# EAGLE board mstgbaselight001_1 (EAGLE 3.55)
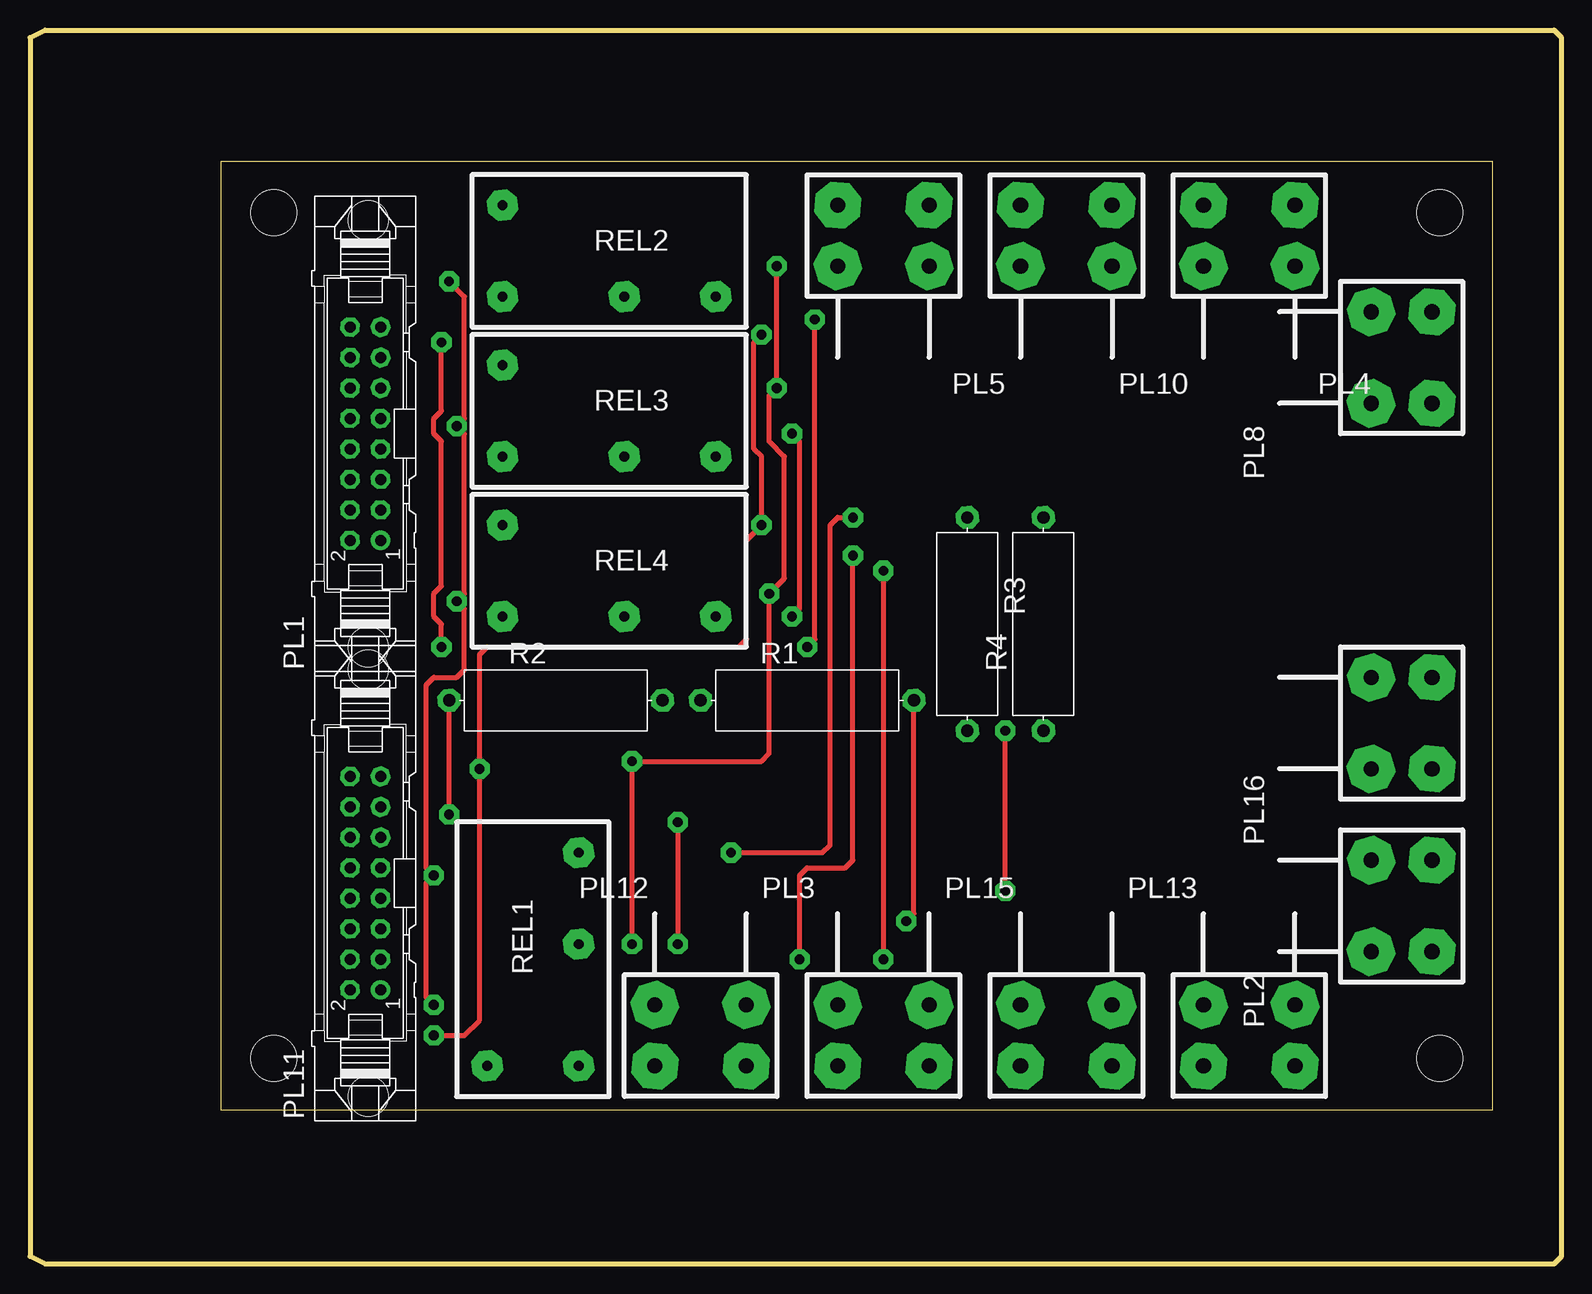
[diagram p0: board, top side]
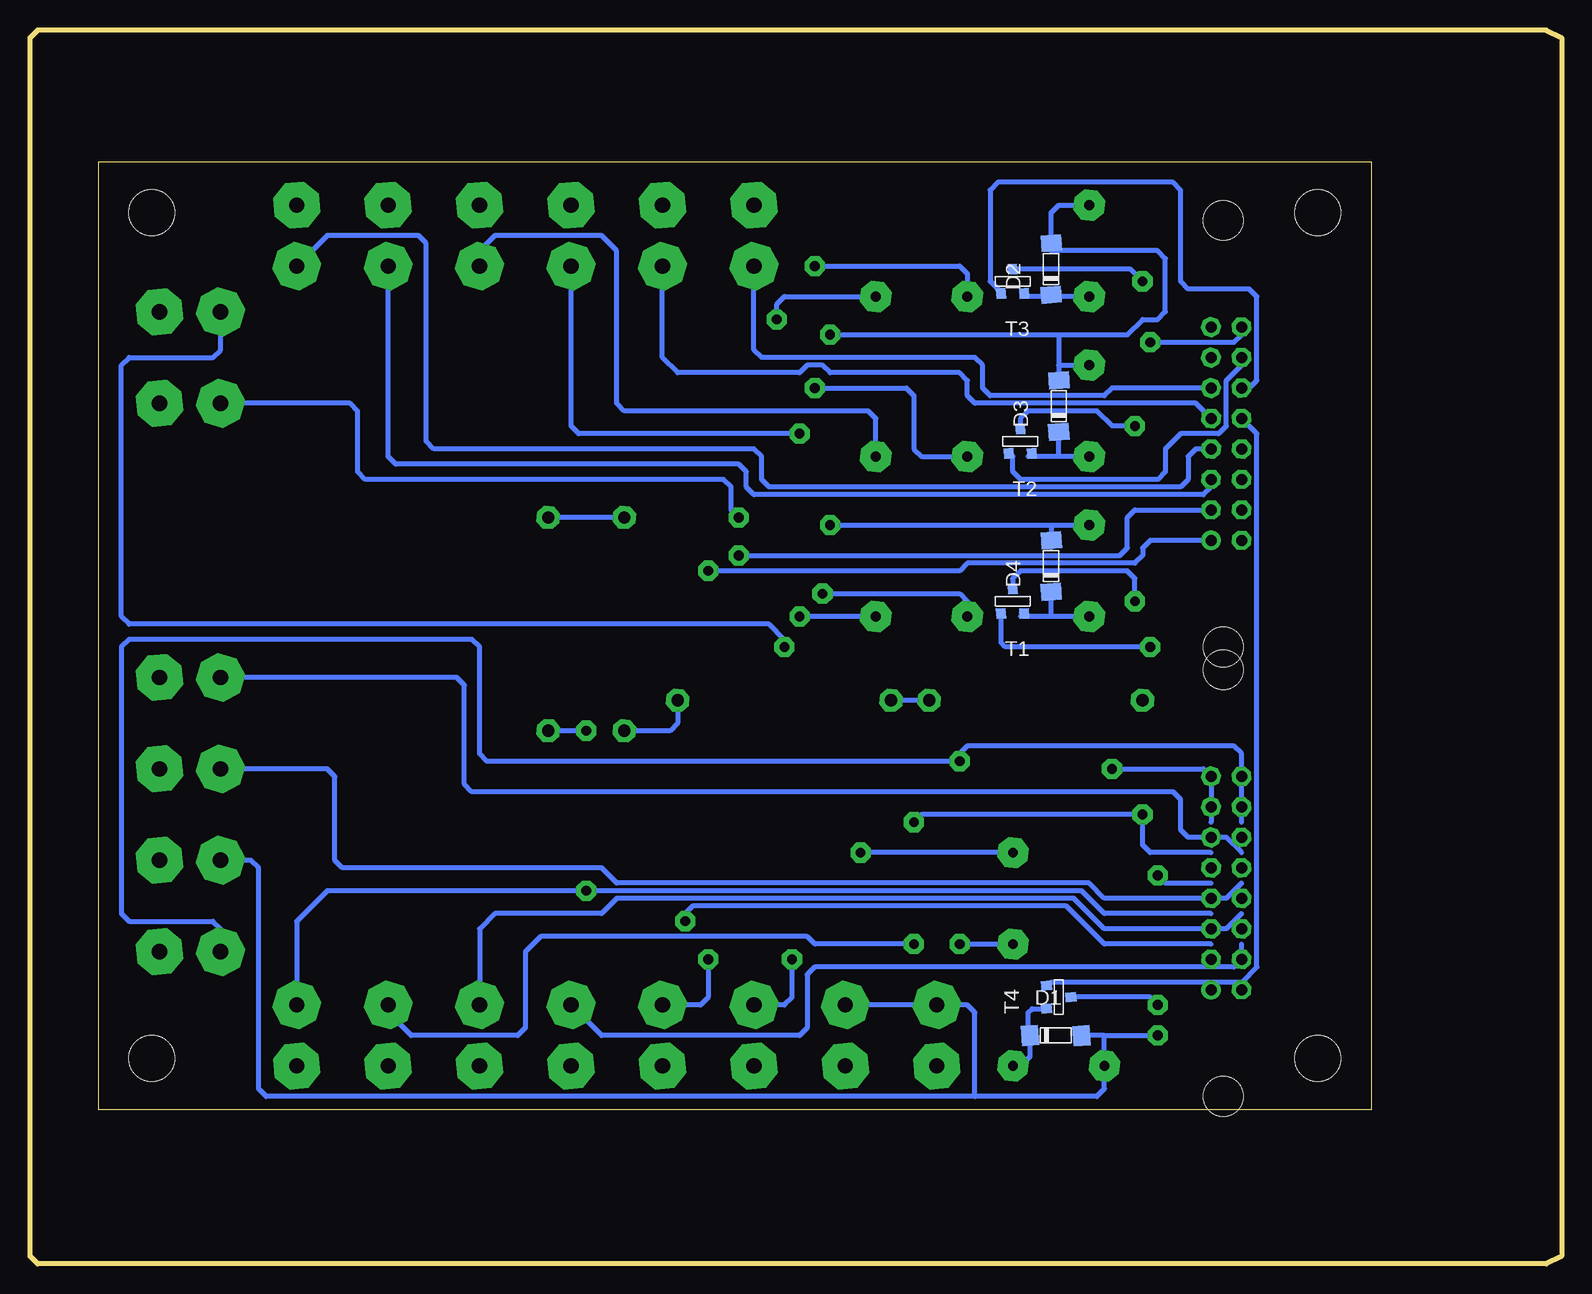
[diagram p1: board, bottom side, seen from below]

Size 127.64 x 102.87 mm. Coordinates in mm from the lower left corner, seen from the top.
Outline: 121.92,12.86 121.92,91.91 15.88,91.91 15.88,12.86 121.92,12.86
Outline: 0,0.63 1.27,0 127,0 127.64,0.63 127.64,102.23 127,102.87 1.27,102.87 0,102.23 0,0.63
Copper layers used: Top, Bottom
Holes 3.81 mm at 20.32,87.63 117.47,87.63 117.47,17.14 20.32,17.14
vRestrict: area 69.9,50.8 to 94,74.9

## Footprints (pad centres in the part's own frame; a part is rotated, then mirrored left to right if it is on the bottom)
D-80 = smd 1.397 x 1.702 rotated 4.4:  -2.388,0 | smd 1.397 x 1.702 rotated 4.3:  1.905,-0.025
V = drill 0.914 pad 1.6 round:  -8.89,-1.27 | drill 0.914 pad 1.6 octagon:  -8.89,1.27;  -6.35,-1.27;  -6.35,1.27;  -3.81,-1.27;  -3.81,1.27;  -1.27,-1.27;  -1.27,1.27;  1.27,-1.27;  1.27,1.27;  3.81,-1.27;  3.81,1.27;  6.35,-1.27;  6.35,1.27;  8.89,-1.27;  8.89,1.27 | hole 3.302: 17.78,-0.254; -17.78,-0.254
3MM = drill 1.27 pad 3.81 octagon:  0,0;  7.62,0;  0,-5.08;  7.62,-5.08
18 = drill 1.016 pad 1.905 octagon:  -8.89,0;  8.89,0
LAIS_R = drill 0.813 pad 2.54 octagon:  -12.7,5.08;  -12.7,-2.54;  -2.54,-2.54;  5.08,-2.54
T-23 = smd 0.787 x 0.889 rotated 4.4:  0.991,1.016 | smd 0.787 x 0.889 rotated 4.3:  -0.94,1.016 | smd 0.787 x 0.889 rotated 4.5:  0.025,-1.016

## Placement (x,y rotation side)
D1  SMD4148  [D-80]  41.91,19.05 0 bottom
D2  SMD4148  [D-80]  42.55,83.19 90 bottom
D3  SMD4148  [D-80]  41.91,71.75 90 bottom
D4  SMD4148  [D-80]  42.55,58.42 90 bottom
PL1  16V  [V]  27.94,69.22 90 top
PL2  6_3MM  [3MM]  111.76,26.04 90 top
PL3  6_3MM  [3MM]  67.31,21.59 0 top
PL4  6_3MM  [3MM]  105.41,83.19 180 top
PL5  6_3MM  [3MM]  74.93,83.19 180 top
PL8  6_3MM  [3MM]  111.76,71.75 90 top
PL10  6_3MM  [3MM]  90.17,83.19 180 top
PL11  10V  [V]  27.94,31.75 90 top
PL12  6_3MM  [3MM]  52.07,21.59 0 top
PL13  6_3MM  [3MM]  97.79,21.59 0 top
PL15  6_3MM  [3MM]  82.55,21.59 0 top
PL16  6_3MM  [3MM]  111.76,41.27 90 top
R1  56R 0,5W  [18]  64.77,46.99 0 top
R2  47R 0,5W  [18]  43.81,46.99 0 top
R3  82R 0,5W  [18]  78.1,53.34 270 top
R4  68R 0,5W  [18]  84.45,53.34 90 top
REL1  REL_RE  [LAIS_R]  43.18,29.21 90 top
REL2  REL_RE  [LAIS_R]  52.07,83.19 0 top
REL3  REL_RE  [LAIS_R]  52.07,69.85 0 top
REL4  REL_RE  [LAIS_R]  52.07,56.52 0 top
T1  FDV301N  [T-23]  45.72,55.25 180 bottom
T2  FDV301N  [T-23]  45.09,68.58 180 bottom
T3  FDV301N  [T-23]  45.72,81.92 180 bottom
T4  FDV301N  [T-23]  41.91,22.23 90 bottom

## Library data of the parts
D1-D4 T1-T4 = smd
PL1 PL11 = pinh-v
PL2-PL5 PL8 PL10 PL12 PL13 PL15 PL16 REL1-REL4 = andit4at
R1-R4 = discrete

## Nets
N$1: PL2. PL11. REL1. REL2. REL3. REL4.
N$2: D1. D2. D3. D4. PL2. PL11. PL12. REL1. REL2. REL3. REL4.
N$3: PL1. T3.
N$4: PL1. T2.
N$5: PL1. T4.
N$6: PL1. T1.
N$7: R3. R4.
N$9: D2. REL2. T3.
N$10: D3. REL3. T2.
N$11: PL10. REL4.
N$12: PL10. REL3.
N$13: PL8. REL2.
N$15: PL8. REL1.
N$16: D1. REL1. T4.
N$17: D4. REL4. T1.
N$18: R1. R2.
N$19: PL11. T1. T2. T3. T4.
N$20: PL11. R1. R3.
N$24: PL1. PL5.
N$25: PL1. PL5.
N$26: PL1. PL4.
N$27: PL1. PL4.
N$28: PL1. PL3.
N$29: PL1. PL3.
N$31: PL11. PL13. R2.
N$33: PL11. PL13. R4.
N$37: PL11. PL16.
N$38: PL11. PL16.
N$39: PL11. PL15.
N$40: PL11. PL15.

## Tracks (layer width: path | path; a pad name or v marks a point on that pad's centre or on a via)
N$1  (via drill 0.81 pad 1.68)
  Top 0.406: v62.23,83.19 v62.23,73.03 61.59,72.39 61.59,68.58 62.87,67.31 62.87,57.15 v61.59,55.88 61.59,42.55 60.96,41.91 v50.16,41.91 v50.16,26.67
  Bottom 0.406: 26.67,36.83 26.67,42.55 27.3,43.18 49.53,43.18 50.16,42.55 v50.16,41.91 89.53,41.91 90.17,42.55 90.17,51.44 90.81,52.07 119.38,52.07 120.02,51.44 120.02,29.21 119.38,28.57 112.39,28.57 111.76,27.94 111.76,26.04 | 49.53,80.64 49.53,82.55 50.16,83.19 v62.23,83.19 | 49.53,67.31 53.34,67.31 53.98,67.94 53.98,72.39 54.61,73.03 v62.23,73.03 | 49.53,53.97 49.53,55.25 50.16,55.88 v61.59,55.88 | v50.16,26.67 45.72,26.67
N$2  (via drill 0.81 pad 1.68)
  Top 0.406: v33.66,19.05 36.2,19.05 37.47,20.32 v37.47,41.27 37.47,50.8 38.1,51.44 59.05,51.44 59.69,52.07 59.69,60.33 v60.96,61.59 60.96,67.31 60.33,67.94 60.33,76.84 v60.96,77.47
  Bottom 0.254: 42.55,85.09 D2.
  Bottom 0.406: 111.76,33.66 109.22,33.66 108.58,33.02 108.58,14.6 107.95,13.97 48.9,13.97 | 38.1,19.05 38.1,16.51 38.1,14.6 38.73,13.97 48.9,13.97 | D1. 40,19.05 38.1,19.05 | 39.37,88.27 41.91,88.27 42.55,87.63 42.55,85.09 42.55,84.45 33.66,84.45 33.02,83.82 33.02,79.38 33.66,78.74 34.92,78.74 36.2,77.47 41.91,77.47 | 42.55,61.59 39.37,61.59 v60.96,61.59 42.55,61.59 | 42.55,61.59 42.55,60.33 | 42.55,60.33 42.55,59.69 | 29.21,36.83 29.21,40.64 29.84,41.27 v37.47,41.27 | 59.69,21.59 52.07,21.59 49.53,21.59 48.9,20.95 48.9,13.97 | 38.1,19.05 v33.66,19.05 | 41.91,77.47 41.91,74.93 | 41.91,74.93 39.37,74.93 | 41.91,74.93 41.91,73.66 | 41.91,77.47 41.91,73.66 | v60.96,77.47 41.91,77.47 | 42.55,60.33 D4. | 41.91,73.66 D3.
N$3
  Bottom 0.406: 26.67,73.03 26.04,73.03 25.4,73.66 25.4,80.64 26.04,81.28 31.12,81.28 31.75,81.92 31.75,89.53 32.39,90.17 46.99,90.17 47.62,89.53 47.62,81.92 46.71,81 46.71,80.9
N$4
  Bottom 0.406: 26.67,75.56 26.67,74.93 27.94,73.66 27.94,69.85 28.57,69.22 31.75,69.22 33.02,67.94 33.02,66.04 33.66,65.41 45.09,65.41 45.72,66.04 45.72,67.31 45.97,67.56 46.08,67.56
N$5
  Bottom 0.406: 26.67,70.48 25.4,69.22 25.4,24.77 26.67,23.49 42.55,23.49 42.93,23.11 | 42.93,23.11 43.18,22.86 | 42.93,23.11 42.93,23.22
N$6  (via drill 0.81 pad 1.68)
  Top 0.406: v34.29,51.44 34.29,53.34 33.66,53.97 33.66,55.88 34.29,56.52 34.29,68.58 33.66,69.22 33.66,70.48 34.29,71.12 v34.29,76.84
  Bottom 0.406: PL1. 26.67,77.47 27.3,76.84 v34.29,76.84 | 46.71,54.23 46.71,51.79 46.36,51.44 v34.29,51.44
N$7
  Bottom 0.406: 78.1,62.23 R4.
N$9
  Bottom 0.254: 42.55,80.64 42.55,80.8
  Bottom 0.406: 39.37,80.64 42.55,80.64 44.45,80.64 44.7,80.9 | 44.7,80.9 44.78,80.98 | 44.7,80.9 44.78,80.9
N$10
  Bottom 0.406: 39.37,67.31 41.91,67.31 | 41.91,67.31 41.91,69.37 | 44.14,67.56 44.2,67.56 44.45,67.31 41.91,67.31
N$11  (via drill 0.81 pad 1.68)
  Top 0.406: v63.5,53.97 64.13,54.61 64.13,68.58 v63.5,69.22
  Bottom 0.406: 82.55,83.19 82.55,69.85 81.92,69.22 v63.5,69.22 | REL4. v63.5,53.97
N$12
  Bottom 0.406: 90.17,82.55 90.17,83.19 90.17,84.45 88.9,85.73 80.01,85.73 78.74,84.45 78.74,71.75 78.1,71.12 57.78,71.12 57.15,70.48 REL3.
N$13  (via drill 0.81 pad 1.68)
  Top 0.406: v64.77,51.44 65.41,52.07 v65.41,78.74
  Bottom 0.406: v64.77,51.44 64.77,52.07 66.04,53.34 119.38,53.34 120.02,53.97 120.02,74.93 119.38,75.56 112.39,75.56 111.76,76.2 111.76,79.38 | v65.41,78.74 65.41,80.01 64.77,80.64 REL2.
N$15  (via drill 0.81 pad 1.68)
  Top 0.406: v68.58,62.23 67.31,62.23 66.67,61.59 66.67,34.92 66.04,34.29 v58.42,34.29
  Bottom 0.406: 111.76,71.75 100.97,71.75 100.33,71.12 100.33,66.04 99.69,65.41 69.85,65.41 69.22,64.77 69.22,62.86 v68.58,62.23 | REL1. v58.42,34.29
N$16
  Bottom 0.406: 42.93,21.29 44.12,21.29 44.45,20.95 44.45,19.05 44.3,19.05 44.3,17.3 45.09,16.51 45.72,16.51
N$17
  Bottom 0.254: 44.78,54.23 44.83,54.23 45.09,53.97
  Bottom 0.406: 39.37,53.97 42.55,53.97 | 42.55,53.97 42.55,56.03 | 42.55,53.97 45.09,53.97
N$18
  Bottom 0.406: R2. 55.88,46.99
N$19  (via drill 0.81 pad 1.68)
  Top 0.406: v34.92,81.92 36.2,80.64 36.2,70.48 v35.56,69.85 36.2,69.22 36.2,55.88 v35.56,55.25 36.2,54.61 36.2,49.53 35.56,48.89 33.66,48.89 33.02,48.26 33.02,33.02 v33.66,32.38 33.02,31.75 33.02,22.23 v33.66,21.59
  Bottom 0.406: T3. 35.94,82.93 v34.92,81.92 | T2. 45.11,70.46 44.45,71.12 38.73,71.12 37.47,69.85 v35.56,69.85 | T1. 45.75,57.12 45.09,57.78 36.2,57.78 35.56,57.15 v35.56,55.25 | T4. 34.31,22.25 v33.66,21.59 | v33.66,32.38 33.02,31.75 29.21,31.75
N$20  (via drill 0.81 pad 1.68)
  Top 0.406: v73.03,28.57 73.66,29.21 R1.
  Bottom 0.406: R1. 73.66,45.08 74.3,44.45 R3. | 29.21,26.67 38.1,26.67 41.27,29.84 72.39,29.84 73.03,29.21 v73.03,28.57
N$24
  Bottom 0.406: 67.31,83.19 67.31,76.2 66.67,75.56 48.9,75.56 48.26,74.93 48.26,73.03 47.62,72.39 38.1,72.39 37.47,73.03 29.21,73.03
N$25
  Bottom 0.406: 74.93,83.19 74.93,75.56 73.66,74.3 63.5,74.3 62.87,74.93 61.59,74.93 60.96,74.3 50.16,74.3 49.53,73.66 49.53,72.39 48.9,71.75 30.48,71.75 29.21,70.48
N$26
  Bottom 0.406: 29.21,67.94 30.48,67.94 31.12,67.31 31.12,65.41 31.75,64.77 66.04,64.77 66.67,65.41 66.67,67.31 67.31,67.94 93.98,67.94 94.61,68.58 94.61,85.09 95.25,85.73 102.87,85.73 105.41,83.19
N$27
  Bottom 0.406: 29.21,65.41 29.21,64.77 29.84,64.14 67.31,64.14 67.94,64.77 67.94,66.04 68.58,66.67 97.16,66.67 97.79,67.31 97.79,83.19
N$28  (via drill 0.81 pad 1.68)
  Top 0.406: v64.13,25.4 64.13,32.38 64.77,33.02 67.94,33.02 68.58,33.66 v68.58,59.05
  Bottom 0.406: 67.31,21.59 64.77,21.59 64.13,22.23 v64.13,25.4 | v68.58,59.05 36.83,59.05 36.2,59.69 36.2,62.23 35.56,62.86 29.21,62.86
N$29  (via drill 0.81 pad 1.68)
  Top 0.406: v71.12,57.78 v71.12,25.4
  Bottom 0.406: v71.12,25.4 71.12,22.23 71.75,21.59 74.93,21.59 | v71.12,57.78 50.16,57.78 49.53,58.42 35.56,58.42 34.92,59.05 34.92,59.69 34.29,60.33 29.21,60.33
N$31  (via drill 0.81 pad 1.68)
  Top 0.406: v53.98,36.83 v53.98,26.67 | v34.92,37.47 34.92,46.99
  Bottom 0.406: 29.21,34.29 34.29,34.29 34.92,34.92 v34.92,37.47 53.34,37.47 v53.98,36.83 | v53.98,26.67 62.23,26.67 62.87,27.3 85.09,27.3 86.36,26.04 86.36,19.68 87,19.05 95.89,19.05 97.79,20.95 97.79,21.59
N$33  (via drill 0.81 pad 1.68)
  Top 0.406: v81.28,31.11 v81.28,44.45
  Bottom 0.406: 29.21,29.21 38.1,29.21 40,31.11 v81.28,31.11 | v81.28,31.11 102.87,31.11 105.41,28.57 105.41,21.59 | v81.28,44.45 84.45,44.45 | v81.28,31.11 80.64,31.11
N$37
  Bottom 0.406: 26.67,34.29 27.94,35.56 31.12,35.56 31.75,36.2 31.75,38.73 32.39,39.37 90.81,39.37 91.44,40 91.44,48.26 92.08,48.89 111.76,48.89
N$38
  Bottom 0.406: 26.67,31.75 27.94,30.48 38.1,30.48 39.37,31.75 78.74,31.75 80.01,33.02 101.6,33.02 102.23,33.66 102.23,40.64 102.87,41.27 111.76,41.27
N$39
  Bottom 0.406: 26.67,29.21 27.94,27.94 38.1,27.94 40.64,30.48 78.74,30.48 80.01,29.21 88.9,29.21 90.17,27.94 90.17,21.59
N$40
  Bottom 0.406: 26.67,26.67 26.67,25.4 27.3,24.77 62.23,24.77 62.87,24.13 62.87,19.68 63.5,19.05 80.01,19.05 82.55,21.59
